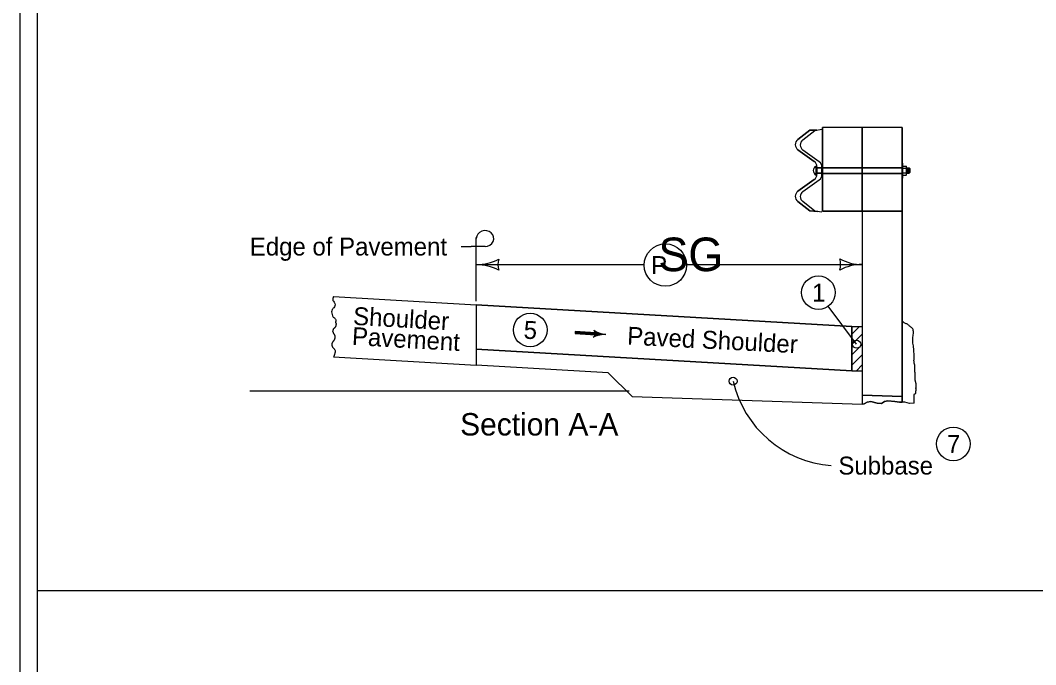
# Model space of a CAD drawing. Extents: x 9538 to 81668, y 7600 to 11751.
# Drawn here: x 20933 to 21839, y 8774 to 9349 of the extents above; entities that cross this region are included whole.
import ezdxf

# ---------------------------------------------------------------- set-up
doc = ezdxf.new("R2010")
doc.units = 0
for name, color, linetype in [('Default', 7, 'Continuous'), ('DsnShtMinorGrid13', 7, 'Continuous'), ('DsnShtMinorGrid14', 7, 'Continuous'), ('dsnStdCells', 7, 'Continuous'), ('dsnStdDimension', 7, 'Continuous'), ('dsnStdNameDate', 7, 'Continuous'), ('dsnStdNote', 7, 'Continuous'), ('dsnStdShading', 7, 'Continuous'), ('dsnStdTable', 7, 'Continuous')]:
    doc.layers.add(name, color=color, linetype=linetype)

msp = doc.modelspace()

# ---------------------------------------------------------------- linework, layer by layer
at = {"layer": 'Default'}
msp.add_lwpolyline([(20932.54, 9944.02), (24067.55, 9944.02), (24067.55, 7924.02), (20932.54, 7924.02)], close=True, dxfattribs=at)
at = {"layer": 'DsnShtMinorGrid13'}
for centre, radius in [((21644.81, 9106.23), 15), ((21387.6, 9072.86), 15), ((21678.93, 9060.11), 3.58), ((21765.25, 8971.18), 15)]:
    msp.add_circle(centre, radius, dxfattribs=at)
at = {"layer": 'DsnShtMinorGrid14'}
msp.add_circle((21568.62, 9027.15), 3.54, dxfattribs=at)
at = {"layer": 'dsnStdCells'}
for p, q in [((21626.57, 9233.67), (21641.08, 9223.26)), ((21641.08, 9207.18), (21626.57, 9196.77))]:
    msp.add_line(p, q, dxfattribs=at)
for points in [[(21683.87, 9217.88), (21683.87, 9253.55), (21648.32, 9253.55), (21648.32, 9217.88), (21648.32, 9217.88), (21683.87, 9217.88)], [(21719.41, 9217.88), (21719.41, 9221.88), (21719.41, 9253.55), (21683.87, 9253.55), (21683.87, 9217.88), (21719.41, 9217.88)], [(21630.83, 9242.57), (21630.81, 9242.56), (21641.59, 9250.97), (21643.47, 9251.3), (21637.14, 9251.19), (21626.38, 9242.79)], [(21645.53, 9223.04), (21645.56, 9223.02), (21630.99, 9233.48), (21631.02, 9233.45)], [(21643.48, 9218.63), (21643.48, 9217.55), (21647.93, 9217.55), (21647.93, 9218.41), (21647.92, 9218.41)], [(21648.32, 9217.55), (21648.32, 9212.88), (21648.33, 9212.88), (21683.87, 9212.88), (21683.87, 9217.55), (21648.32, 9217.55), (21648.32, 9217.55)], [(21719.41, 9212.88), (21719.41, 9217.55), (21683.87, 9217.55), (21683.87, 9212.88), (21719.41, 9212.88)], [(21631.02, 9196.55), (21630.99, 9196.53), (21645.56, 9206.99), (21645.53, 9206.96)], [(21647.92, 9211.6), (21647.93, 9211.6), (21647.93, 9212.88), (21643.48, 9212.88), (21643.48, 9211.82), (21643.48, 9212.88), (21643.48, 9212.88), (21643.48, 9211.82)], [(21648.32, 9212.55), (21648.32, 9178.9), (21683.87, 9178.9), (21683.87, 9212.55), (21648.32, 9212.55)], [(21719.41, 9178.9), (21719.41, 9208.55), (21719.41, 9212.55), (21683.87, 9212.55), (21683.87, 9178.9), (21719.41, 9178.9)], [(21626.38, 9187.65), (21637.14, 9179.25), (21644.25, 9178.56), (21641.59, 9179.03), (21630.81, 9187.44), (21630.83, 9187.43)], [(21719.41, 9013.57), (21719.41, 9178.9), (21683.87, 9178.9), (21683.87, 9075.94), (21683.87, 9069.25), (21683.87, 9069.25), (21683.87, 9069.25), (21683.87, 9060.02), (21683.87, 9060.02), (21683.87, 9060.02), (21683.87, 9050.88), (21683.87, 9050.88), (21683.87, 9050.88), (21683.87, 9043.95), (21683.87, 9014.73), (21719.41, 9013.57)], [(21719.41, 9013.57), (21683.87, 9014.73), (21683.87, 9006.67), (21685.68, 9006.92), (21688.43, 9008.51), (21691.72, 9009.04), (21697.34, 9007.45), (21701.05, 9007.24), (21703.7, 9009.04), (21706.77, 9009.68), (21713.02, 9008.94), (21717.26, 9008.51), (21719.41, 9008.51), (21719.41, 9013.57)]]:
    msp.add_lwpolyline(points, dxfattribs=at)
msp.add_lwpolyline([(21647.93, 9217.55), (21643.48, 9217.55), (21643.48, 9214.09), (21643.48, 9215.22), (21643.48, 9212.88), (21647.93, 9212.88)], close=True, dxfattribs=at)
for centre, start, end in [((21629.86, 9238.31), 127.75002, 234.69086), ((21634.3, 9238.09), 127.75002, 234.69086), ((21637.8, 9218.63), 0, 54.69099), ((21642.25, 9218.41), 0, 54.69099), ((21637.8, 9211.82), 305.30901, 0), ((21642.25, 9211.6), 305.30901, 0), ((21629.86, 9192.14), 125.30914, 232.24998), ((21634.3, 9191.92), 125.30914, 232.24998)]:
    msp.add_arc(centre, 5.68, start, end, dxfattribs=at)
at = {"layer": 'dsnStdDimension'}
for p, q in [((21339.48, 9131.19), (21489.31, 9131.19)), ((21527.16, 9131.34), (21683.87, 9131.34))]:
    msp.add_line(p, q, dxfattribs=at)
msp.add_circle((21508.24, 9130.78), 18.93, dxfattribs=at)
for centre, radius, start, end in [((21339.48, 9173.69), 42.5, 270, 298.07249), ((21375.11, 9131.19), 16.42, 162.26665, 197.73335), ((21648.23, 9131.34), 16.42, 342.26665, 17.73335), ((21683.87, 9173.84), 42.5, 241.92751, 270), ((21339.48, 9088.69), 42.5, 61.92751, 90), ((21683.87, 9088.84), 42.5, 90, 118.07249), ((21663.84, 9049.27), 97.76, 193.07698, 265.55799)]:
    msp.add_arc(centre, radius, start, end, dxfattribs=at)
at = {"layer": 'dsnStdNameDate'}
for p, q in [((21678.93, 9060.11), (21653.55, 9094.04)), ((23103.12, 8840.02), (20947.54, 8840.02))]:
    msp.add_line(p, q, dxfattribs=at)
at = {"layer": 'dsnStdNote'}
for p, q in [((21339.48, 9134.51), (21339.48, 9155.37)), ((21326.11, 9147.35), (21334.79, 9147.35)), ((21347.29, 9147.35), (21334.79, 9147.35)), ((21339.48, 9098.57), (21339.48, 9134.51)), ((21445.86, 9069.47), (21427.66, 9070.52)), ((21445.76, 9068.53), (21445.76, 9068.53)), ((21445.87, 9070.47), (21445.87, 9070.47))]:
    msp.add_line(p, q, dxfattribs=at)
for points in [[(21445.89, 9070.41), (21427.72, 9071.46), (21427.59, 9069.58), (21445.76, 9068.53), (21445.81, 9070.14), (21427.94, 9071.23), (21427.88, 9069.74), (21445.38, 9068.79), (21445.5, 9069.91), (21428.17, 9070.97), (21428.15, 9069.97), (21445.16, 9068.99), (21445.26, 9069.69), (21428.36, 9070.75), (21428.35, 9070.19), (21444.95, 9069.25)], [(21445.48, 9071.66), (21446.18, 9070.5), (21446.16, 9068.85), (21445.4, 9067.45), (21448.15, 9068.32), (21451.35, 9068.97), (21452.25, 9069.1), (21450, 9069.65), (21446.78, 9070.88), (21445.83, 9071.41), (21445.95, 9067.9), (21450.9, 9069.12), (21446.26, 9070.7), (21446.28, 9068.28), (21449.67, 9069.21), (21446.67, 9070.07), (21446.44, 9068.69), (21448.6, 9069.19), (21447.01, 9069.7), (21446.88, 9069.04), (21447.66, 9069.2)]]:
    msp.add_lwpolyline(points, dxfattribs=at)
for centre, major_axis, start_param, end_param in [((21347.29, 9154.49), (-7.81, 0), 1.570796, 6.283185), ((21442.09, 9069.68), (3.88, 0), 5.202895, 7.237436), ((21457.15, 9089.11), (-22.17, 0), 0.954258, 1.478381), ((21454.36, 9048.69), (22.17, 0), 1.537172, 2.061295)]:
    msp.add_ellipse(centre, major_axis=major_axis, ratio=0.913811, start_param=start_param, end_param=end_param, dxfattribs=at)
at = {"layer": 'dsnStdShading'}
msp.add_line((20947.54, 9929.02), (20947.54, 8319.02), dxfattribs=at)
at = {"layer": 'dsnStdTable'}
for p, q in [((21641.59, 9250.97), (21647.93, 9252.09)), ((21719.41, 9253.55), (21648.32, 9253.55)), ((21648.32, 9178.9), (21648.32, 9253.55)), ((21683.87, 9178.9), (21683.87, 9253.55)), ((21719.41, 9253.55), (21719.41, 9008.51)), ((21626.38, 9242.79), (21637.14, 9251.19)), ((21630.81, 9242.56), (21641.59, 9250.97)), ((21637.14, 9251.19), (21643.47, 9251.3)), ((21641.08, 9223.26), (21626.57, 9233.67)), ((21645.56, 9223.02), (21630.99, 9233.48)), ((21642.71, 9211.15), (21642.71, 9219.24)), ((21642.71, 9217.55), (21648.14, 9217.55)), ((21643.48, 9211.82), (21643.48, 9218.63)), ((21643.65, 9217.55), (21648.32, 9217.55)), ((21647.93, 9215), (21647.93, 9218.41)), ((21648.32, 9217.88), (21719.41, 9217.88)), ((21648.32, 9217.55), (21719.41, 9217.55)), ((21719.41, 9221.85), (21720.09, 9221.85)), ((21720.1, 9208.52), (21720.09, 9221.85)), ((21720.09, 9217.2), (21723.06, 9217.2)), ((21720.1, 9219.23), (21723.06, 9219.23)), ((21723.43, 9212.15), (21723.43, 9218.21)), ((21723.43, 9217.52), (21725.8, 9217.52)), ((21724.32, 9217.52), (21724.32, 9212.85)), ((21725.06, 9217.52), (21725.06, 9212.85)), ((21725.8, 9217.52), (21726.24, 9216.98)), ((21725.8, 9217.52), (21725.8, 9212.85)), ((21726.24, 9216.98), (21726.24, 9213.39)), ((21626.57, 9196.77), (21641.08, 9207.18)), ((21630.99, 9196.53), (21645.56, 9206.99)), ((21642.71, 9212.88), (21648.32, 9212.88)), ((21643.48, 9211.82), (21643.48, 9215.22)), ((21643.48, 9215.22), (21643.48, 9211.82)), ((21647.93, 9211.6), (21647.93, 9215)), ((21647.93, 9215), (21647.93, 9211.6)), ((21648.32, 9212.55), (21719.41, 9212.55)), ((21648.33, 9212.88), (21719.41, 9212.88)), ((21719.41, 9208.52), (21720.1, 9208.52)), ((21720.09, 9213.16), (21723.06, 9213.16)), ((21720.09, 9211.14), (21723.06, 9211.14)), ((21723.43, 9212.85), (21725.8, 9212.85)), ((21726.24, 9213.39), (21725.8, 9212.85)), ((21637.14, 9179.25), (21626.38, 9187.65)), ((21641.59, 9179.03), (21630.81, 9187.44)), ((21644.25, 9178.56), (21637.14, 9179.25)), ((21647.93, 9177.92), (21641.59, 9179.03)), ((21683.87, 9178.9), (21648.32, 9178.9)), ((21683.87, 9178.9), (21683.87, 9006.67)), ((21212.01, 9102.84), (21339.48, 9095.43)), ((21339.48, 9095.43), (21339.48, 9041.42)), ((21339.48, 9095.43), (21674.61, 9075.94)), ((21674.61, 9075.94), (21339.48, 9095.43)), ((21339.48, 9095.43), (21339.48, 9055.83)), ((21674.61, 9069.2), (21681.36, 9075.94)), ((21674.61, 9069.2), (21681.36, 9075.94)), ((21674.61, 9069.2), (21681.36, 9075.94)), ((21674.61, 9069.2), (21681.36, 9075.94)), ((21674.61, 9075.94), (21683.85, 9075.94)), ((21674.61, 9075.94), (21674.61, 9036.51)), ((21674.61, 9036.51), (21674.61, 9075.94)), ((21674.61, 9060.01), (21683.85, 9069.25)), ((21674.61, 9060.01), (21683.85, 9069.25)), ((21674.61, 9060.01), (21683.85, 9069.25)), ((21674.61, 9060.01), (21683.85, 9069.25)), ((21729.46, 9069.17), (21729.46, 9069.17)), ((21674.61, 9036.51), (21339.48, 9055.83)), ((21339.48, 9055.83), (21674.61, 9036.51)), ((21674.61, 9050.78), (21683.85, 9060.02)), ((21674.61, 9050.78), (21683.85, 9060.02)), ((21674.61, 9050.78), (21683.85, 9060.02)), ((21674.61, 9050.78), (21683.85, 9060.02)), ((21212.04, 9048.83), (21339.48, 9041.42)), ((21674.61, 9041.56), (21683.85, 9050.79)), ((21457.31, 9034.62), (21339.48, 9041.42)), ((21457.31, 9034.62), (21478.65, 9013.41)), ((21674.61, 9036.51), (21683.85, 9036.51)), ((21678.71, 9036.51), (21683.85, 9041.65)), ((21137.42, 9018.58), (21475.92, 9018.58)), ((21478.65, 9013.41), (21683.87, 9006.67))]:
    msp.add_line(p, q, dxfattribs=at)
for points in [[(21723.13, 9217.21), (21723.2, 9217.25), (21723.27, 9217.35), (21723.35, 9217.57), (21723.41, 9217.86), (21723.41, 9215.91), (21723.36, 9216.43), (21723.3, 9216.8), (21723.19, 9217.12), (21723.13, 9217.21), (21723.18, 9217.21), (21723.29, 9217.36), (21723.37, 9217.59), (21723.4, 9217.74), (21723.4, 9216.2), (21723.32, 9216.7), (21723.27, 9216.96), (21723.16, 9217.18), (21723.2, 9217.2), (21723.33, 9217.41), (21723.37, 9217.57), (21723.38, 9216.46), (21723.19, 9217.17), (21723.35, 9217.45), (21723.36, 9216.6), (21723.21, 9217.16), (21723.34, 9217.38), (21723.34, 9216.74), (21723.23, 9217.14), (21723.32, 9217.32), (21723.32, 9216.9), (21723.25, 9217.13), (21723.3, 9217.25), (21723.31, 9217.04), (21723.27, 9217.11), (21723.29, 9217.16)], [(21723.41, 9212.48), (21723.37, 9212.74), (21723.32, 9212.92), (21723.23, 9213.07), (21723.12, 9213.17), (21723.19, 9213.26), (21723.28, 9213.49), (21723.34, 9213.8), (21723.42, 9214.55), (21723.41, 9212.47), (21723.39, 9212.62), (21723.35, 9212.83), (21723.27, 9213.04), (21723.16, 9213.15), (21723.2, 9213.24), (21723.26, 9213.39), (21723.36, 9213.89), (21723.4, 9214.27), (21723.39, 9212.67), (21723.37, 9212.79), (21723.32, 9212.95), (21723.19, 9213.15), (21723.25, 9213.32), (21723.32, 9213.66), (21723.38, 9213.98), (21723.37, 9212.82), (21723.33, 9212.95), (21723.22, 9213.14), (21723.27, 9213.36), (21723.32, 9213.62), (21723.36, 9213.79), (21723.35, 9212.93), (21723.29, 9213.03), (21723.25, 9213.15), (21723.34, 9213.61), (21723.33, 9213.01), (21723.27, 9213.14), (21723.31, 9213.44), (21723.31, 9213.08), (21723.28, 9213.15), (21723.29, 9213.25), (21723.29, 9213.18)], [(21729.93, 9045.33), (21729.88, 9045.06), (21729.88, 9044.86), (21729.88, 9044.67), (21729.88, 9044.47), (21729.88, 9044.28), (21729.88, 9044.08), (21729.88, 9043.79), (21729.88, 9043.59), (21729.97, 9043.3), (21730.07, 9043.01), (21730.27, 9042.81), (21730.27, 9042.62), (21730.36, 9042.42), (21730.36, 9042.23), (21730.36, 9042.03), (21730.46, 9041.93), (21730.46, 9041.74), (21730.46, 9041.54), (21730.46, 9041.35), (21730.46, 9041.15), (21730.46, 9040.96), (21730.46, 9040.66), (21730.46, 9040.37), (21730.46, 9040.17), (21730.46, 9039.88), (21730.46, 9039.69), (21730.46, 9039.49), (21730.56, 9039.39), (21730.56, 9039.2), (21730.56, 9039), (21730.56, 9038.81), (21730.56, 9038.61), (21730.56, 9038.42), (21730.56, 9038.22), (21730.56, 9038.02), (21730.56, 9037.83), (21730.56, 9037.63), (21730.56, 9037.44), (21730.56, 9037.24), (21730.56, 9037.05), (21730.56, 9036.85), (21730.56, 9036.66), (21730.56, 9036.46), (21730.56, 9036.27), (21730.56, 9036.07), (21730.56, 9035.88), (21730.66, 9035.78), (21730.66, 9035.58), (21730.66, 9035.39), (21730.76, 9035.29), (21730.76, 9035.09), (21730.76, 9034.9), (21730.85, 9034.8), (21730.85, 9034.61), (21730.85, 9034.41), (21730.85, 9034.21), (21730.85, 9033.92), (21730.95, 9033.63), (21730.95, 9033.43), (21730.95, 9033.24), (21730.95, 9033.04), (21730.95, 9032.85), (21730.95, 9032.65), (21730.95, 9032.46), (21730.95, 9032.26), (21730.95, 9032.06), (21730.95, 9031.87), (21730.95, 9031.67), (21730.95, 9031.48), (21730.95, 9031.28), (21730.95, 9031.09), (21730.95, 9030.89), (21730.95, 9030.7), (21730.95, 9030.5), (21730.95, 9030.31), (21730.95, 9030.11), (21730.95, 9029.92), (21730.95, 9029.72), (21730.95, 9029.52), (21730.95, 9029.33), (21730.95, 9029.13), (21730.95, 9028.94), (21730.95, 9028.74), (21730.95, 9028.55), (21730.95, 9028.35), (21730.95, 9028.16), (21730.95, 9027.96), (21731.05, 9027.86), (21731.05, 9027.57), (21731.05, 9027.37), (21731.15, 9027.18), (21731.24, 9026.89), (21731.24, 9026.69), (21731.34, 9026.59), (21731.34, 9026.4), (21731.44, 9026.3), (21731.54, 9026.2), (21731.54, 9026.01), (21731.54, 9025.81), (21731.54, 9025.62), (21731.63, 9025.52), (21731.63, 9025.32), (21731.63, 9025.13), (21731.63, 9024.93), (21731.63, 9024.74), (21731.63, 9024.54), (21731.63, 9024.35), (21731.63, 9024.15), (21731.63, 9023.96), (21731.63, 9023.76), (21731.63, 9023.56), (21731.63, 9023.37), (21731.63, 9023.17), (21731.63, 9022.98), (21731.63, 9022.78), (21731.63, 9022.59), (21731.63, 9022.39), (21731.63, 9022.2), (21731.63, 9022), (21731.63, 9021.81), (21731.63, 9021.61), (21731.63, 9021.42), (21731.63, 9021.22), (21731.63, 9021.02), (21731.63, 9020.83), (21731.63, 9020.63), (21731.63, 9020.63), (21731.63, 9020.93), (21731.63, 9021.12), (21731.63, 9021.32), (21731.63, 9021.12), (21731.63, 9020.93), (21731.63, 9020.73), (21731.63, 9020.54), (21731.63, 9020.34), (21731.63, 9020.14), (21731.63, 9019.95), (21731.63, 9019.75), (21731.63, 9019.56), (21731.63, 9019.36), (21731.63, 9019.17), (21731.63, 9018.97), (21731.63, 9018.78), (21731.63, 9018.58), (21731.63, 9018.39), (21731.54, 9018.29), (21731.54, 9018.09), (21731.54, 9017.9), (21731.54, 9017.7), (21731.54, 9017.51), (21731.54, 9017.31), (21731.54, 9017.12), (21731.54, 9016.92), (21731.54, 9016.73), (21731.54, 9016.53), (21731.54, 9016.33), (21731.44, 9016.24), (21731.34, 9016.04), (21731.24, 9015.94), (21731.15, 9015.85), (21731.05, 9015.75), (21730.85, 9015.65), (21730.66, 9015.65), (21730.56, 9015.55), (21730.46, 9015.46), (21730.36, 9015.36), (21730.17, 9015.26), (21730.07, 9015.16), (21730.07, 9014.97), (21729.97, 9014.87), (21729.97, 9014.67), (21729.97, 9014.48), (21729.97, 9014.28), (21729.97, 9007.46)], [(21730.11, 9007.47), (21725.96, 9007.35), (21721.82, 9008.51), (21717.26, 9008.51), (21713.02, 9008.94), (21706.77, 9009.68), (21703.7, 9009.04), (21701.05, 9007.24), (21697.34, 9007.45), (21691.72, 9009.04), (21688.43, 9008.51), (21685.68, 9006.92), (21683.87, 9006.67)]]:
    msp.add_lwpolyline(points, dxfattribs=at)
msp.add_circle((21387.6, 9072.86), 15, dxfattribs=at)
for centre, radius, start, end in [((21629.86, 9238.31), 5.68, 127.75002, 234.69086), ((21634.3, 9238.09), 5.68, 127.75002, 234.69086), ((21644.78, 9215.2), 4.54, 117.20289, 242.8461), ((21637.8, 9218.63), 5.68, 360, 54.69099), ((21642.25, 9218.41), 5.68, 360, 54.69099), ((21637.8, 9211.82), 5.68, 305.30901, 0), ((21642.25, 9211.6), 5.68, 305.30901, 0), ((21629.86, 9192.14), 5.68, 125.30914, 232.24998), ((21634.3, 9191.92), 5.68, 125.30914, 232.24998)]:
    msp.add_arc(centre, radius, start, end, dxfattribs=at)
for centre in [(21723.06, 9218.21), (21723.06, 9212.15)]:
    msp.add_ellipse(centre, major_axis=(0, -1.01), ratio=0.362258, start_param=6.283156, end_param=9.424748, dxfattribs=at)
for points in [[(21212.01, 9102.84), (21211.51, 9099.24), (21212.55, 9097.73), (21213.42, 9095.44), (21212.81, 9093.38), (21210.9, 9091), (21210.38, 9089.1), (21210.9, 9086.8), (21211.77, 9084.43), (21212.81, 9083.72), (21214.2, 9081.18), (21214.19, 9080.34)], [(21212.22, 9063.23), (21212.43, 9063.48), (21212.63, 9063.74), (21212.98, 9064.3), (21213.27, 9064.89), (21213.38, 9065.19), (21213.48, 9065.51), (21213.62, 9066.13), (21213.66, 9066.75), (21213.62, 9067.34), (21213.56, 9067.61), (21213.52, 9067.75), (21213.47, 9067.88), (21213.27, 9068.26), (21212.98, 9068.62), (21212.68, 9068.99), (21212.43, 9069.38), (21212.3, 9069.67), (21212.16, 9069.95), (21211.9, 9070.52), (21211.69, 9071.09), (21211.62, 9071.38), (21211.57, 9071.68), (21211.56, 9071.81), (21211.56, 9071.94), (21211.71, 9072.71), (21211.92, 9073.23), (21212.17, 9073.74), (21212.62, 9074.38), (21213.14, 9074.92), (21213.65, 9075.47), (21213.88, 9075.78), (21214.08, 9076.12), (21214.29, 9076.59), (21214.44, 9077.06), (21214.55, 9077.54), (21214.58, 9077.78), (21214.59, 9077.9), (21214.6, 9078.02), (21214.55, 9078.53), (21214.4, 9079.04), (21214.35, 9079.17), (21214.3, 9079.29), (21214.25, 9079.42), (21214.22, 9079.55), (21214.19, 9080.34)], [(21729.93, 9045.33), (21730.26, 9048.24), (21730.03, 9053.1), (21729.59, 9058.85), (21728.93, 9063.27), (21729.15, 9066.59), (21729.59, 9070.79), (21728.93, 9073.89), (21726.72, 9075.88), (21724.73, 9077.65), (21722.52, 9078.75), (21720.31, 9080.08), (21719.42, 9080.74)], [(21212.22, 9063.23), (21212.01, 9062.99), (21211.76, 9062.76), (21211.53, 9062.52), (21211.34, 9062.25), (21211.2, 9061.97), (21211.06, 9061.68), (21210.8, 9061.11), (21210.69, 9060.83), (21210.6, 9060.54), (21210.53, 9060.25), (21210.5, 9060.1), (21210.48, 9059.95), (21210.49, 9059.44), (21210.62, 9058.92), (21210.83, 9058.4), (21211.08, 9057.89), (21211.53, 9057.26), (21212.05, 9056.71), (21212.56, 9056.16), (21212.79, 9055.86), (21212.99, 9055.52), (21213.39, 9054.57), (21213.5, 9054.1), (21213.51, 9053.62), (21213.47, 9053.33), (21213.43, 9053.04), (21213.37, 9052.75), (21213.3, 9052.47), (21212.99, 9051.32), (21212.81, 9050.71), (21212.62, 9050.11), (21212.39, 9049.52), (21212.26, 9049.23), (21212.12, 9048.94), (21212.04, 9048.83)]]:
    msp.add_spline(points, degree=3, dxfattribs=at)

# ---------------------------------------------------------------- texts
at = {"layer": 'DsnShtMinorGrid13'}
for s, p in [('1', (21639.18, 9098.23)), ('7', (21759.54, 8963.18))]:
    msp.add_text(s, height=16, dxfattribs=at).set_placement(p)
msp.add_text('5', height=16, rotation=356.69973, dxfattribs=at).set_placement((21381.38, 9065.2))
at = {"layer": 'dsnStdDimension'}
for s, height, p in [('SG', 30, (21501.95, 9125.34)), ('P', 16, (21495.52, 9122.78))]:
    msp.add_text(s, height=height, dxfattribs=at).set_placement(p)
at = {"layer": 'dsnStdNote'}
for s, height, p in [('Edge of Pavement', 16, (21137.35, 9139.35)), ('Section A-A', 20, (21325.05, 8978.66)), ('Subbase', 16, (21662.63, 8943.8))]:
    msp.add_text(s, height=height, dxfattribs=at).set_placement(p)
for s, rotation, p in [('Shoulder', 356.73462, (21229.23, 9077.5)), ('Pavement', 356.73462, (21228.21, 9059.53)), ('Paved Shoulder ', 357.0678, (21473.87, 9059.83))]:
    msp.add_text(s, height=16, rotation=rotation, dxfattribs=at).set_placement(p)

doc.saveas('drawing.dxf')
